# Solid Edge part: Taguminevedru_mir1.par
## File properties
Author: Türk
Template: Iso Part.par
Last saved by: Türk
Revision: 2
Application: Solid Edge
Accuracy: 0,990
Username: Türk
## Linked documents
Taguminevedru.par
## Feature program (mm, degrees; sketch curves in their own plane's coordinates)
part copy "CopiedPart_1"
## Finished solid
Body 1: solid body, 7 faces, 18 edges, 12 vertices.
  Faces by surface: plane 4, torus 2, spline 1
  Edges by curve: circle 10, intersection 6, line 2
Bounding box of the edges (mm; curved faces can reach further): 103.000 x 229.400 x 103.000, from (-51.5, -229.4, -51.5) to (51.5, 0, 51.5).
Toroidal faces (ring radius, tube radius in mm): R45.5 r6 x2
Planar faces by outward normal: +y 1, -y 1, oblique 2
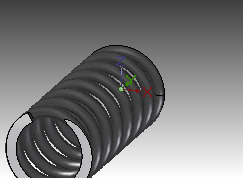
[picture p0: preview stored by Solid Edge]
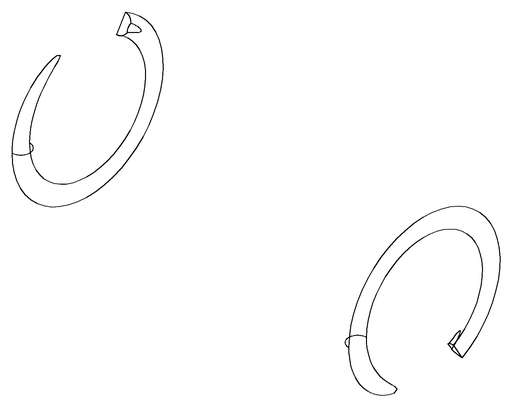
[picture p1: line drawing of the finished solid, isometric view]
